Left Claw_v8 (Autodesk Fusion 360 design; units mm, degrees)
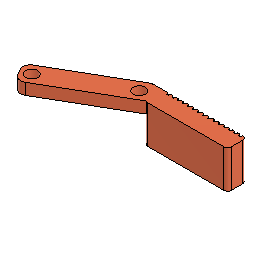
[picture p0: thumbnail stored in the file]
sketch "Sketch1" plane through (0, 0, 0) normal (0, 0, 1) x axis (1, 0, 0)
  line L1 (25, 0) -> (0, 0)
  line L2 (25, 5) -> (25, 0)
  line L3 (0, 5) -> (25, 5)
  line L4 (0, 0) -> (0, 5)
  line L5 (2.8868, 0) -> (0, 5)
  line L6 (-18.7639, -12.5) -> (2.8868, 0)
  line L7 (-21.6506, -7.5) -> (-18.7639, -12.5)
  line L8 (0, 5) -> (-21.6506, -7.5)
  line L9 (1.4434, 2.5) -> (-20.2073, -10)
  line L10 (25, 0) -> (2.8868, 0)
  line L11 (25, 5) -> (25, 0)
  line L12 (2.8868, 5) -> (25, 5)
  line L13 (2.8868, 0) -> (2.8868, 5)
  circle C1 centre (-18.0422, -8.75) radius 1.6
  circle C2 centre (0, 1.6667) radius 1.6
  point P1 (0, 0)
  point P2 (0, 0)
  point P6 (2.8868, 0)
  point P9 (-20.2073, -10)
  point P10 (1.4434, 2.5)
  point P11 (-18.0422, -8.75)
  point P12 (0, 1.6667)
  point P3 (25, 0)
  point P5 (0, 5)
  point P8 (-21.6506, -7.5)
  horizontal L1
  vertical L2
  horizontal L3
  vertical L4
  coincident P1 P2
  perpendicular L5 L6
  parallel L5 L7
  parallel L6 L8
  coincident L1 P6
  midpoint L7 P9
  midpoint L5 P10
  coincident L9 P11
  coincident L4 P12
  coincident L9 P12
  horizontal L10
  vertical L11
  horizontal L12
  vertical L13
  dimension "d1" distance P2 P3 = 25
  dimension "d2" distance P2 P5 = 5
  dimension "d3" distance P5 P8 = 25
  dimension "d4" diameter C1 = 3.2
  dimension "d5" distance L7 P11 = 2.5
  dimension "d8" angle L1 L6 = 150
  dimension "d9" diameter C2 = 3.2
extrude "Extrude1" new body sketch "Sketch1" profile of L1 L3 L4 L5 L6 L7 L8 C1 C2 L13 against normal blind 3
extrude "Extrude5" add sketch "Sketch1" profile of L1 L2 L3 L10 L11 L12 L13 against normal blind 10
sketch "Sketch2" plane through (0, 0, 0) normal (0, 0, 1) x axis (-1, 0, 0)
  line L1 (0, -5) -> (-25, -5)
  line L2 (21.6506, 7.5) -> (0, -5)
  line L3 (18.7639, 12.5) -> (21.6506, 7.5)
  line L4 (-2.8868, 0) -> (18.7639, 12.5)
  line L5 (-25, 0) -> (-2.8868, 0)
  line L6 (-25, -5) -> (-25, 0)
  line L7 (-23.4493, -4.5) -> (-23.2, -5)
  line L8 (-23.4493, -4.5) -> (-23.7507, -4.5)
  line L9 (-23.7507, -4.5) -> (-24, -5)
  line L10 (-22.3936, -4.5) -> (-22.6429, -5)
  line L11 (-22.0922, -4.5) -> (-22.3936, -4.5)
  line L12 (-22.0922, -4.5) -> (-21.8429, -5)
  line L13 (-21.0364, -4.5) -> (-21.2857, -5)
  line L14 (-20.735, -4.5) -> (-21.0364, -4.5)
  line L15 (-20.735, -4.5) -> (-20.4857, -5)
  line L16 (-19.6793, -4.5) -> (-19.9286, -5)
  line L17 (-19.3779, -4.5) -> (-19.6793, -4.5)
  line L18 (-19.3779, -4.5) -> (-19.1286, -5)
  line L19 (-18.3221, -4.5) -> (-18.5714, -5)
  line L20 (-18.0207, -4.5) -> (-18.3221, -4.5)
  line L21 (-18.0207, -4.5) -> (-17.7714, -5)
  line L22 (-16.965, -4.5) -> (-17.2143, -5)
  line L23 (-16.6636, -4.5) -> (-16.965, -4.5)
  line L24 (-16.6636, -4.5) -> (-16.4143, -5)
  line L25 (-15.6078, -4.5) -> (-15.8571, -5)
  line L26 (-15.3064, -4.5) -> (-15.6078, -4.5)
  line L27 (-15.3064, -4.5) -> (-15.0571, -5)
  line L28 (-14.2507, -4.5) -> (-14.5, -5)
  line L29 (-13.9493, -4.5) -> (-14.2507, -4.5)
  line L30 (-13.9493, -4.5) -> (-13.7, -5)
  line L31 (-12.8936, -4.5) -> (-13.1429, -5)
  line L32 (-12.5922, -4.5) -> (-12.8936, -4.5)
  line L33 (-12.5922, -4.5) -> (-12.3429, -5)
  line L34 (-11.5364, -4.5) -> (-11.7857, -5)
  line L35 (-11.235, -4.5) -> (-11.5364, -4.5)
  line L36 (-11.235, -4.5) -> (-10.9857, -5)
  line L37 (-10.1793, -4.5) -> (-10.4286, -5)
  line L38 (-9.8779, -4.5) -> (-10.1793, -4.5)
  line L39 (-9.8779, -4.5) -> (-9.6286, -5)
  line L40 (-8.8221, -4.5) -> (-9.0714, -5)
  line L41 (-8.5207, -4.5) -> (-8.8221, -4.5)
  line L42 (-8.5207, -4.5) -> (-8.2714, -5)
  line L43 (-7.465, -4.5) -> (-7.7143, -5)
  line L44 (-7.1636, -4.5) -> (-7.465, -4.5)
  line L45 (-7.1636, -4.5) -> (-6.9143, -5)
  line L46 (-6.1078, -4.5) -> (-6.3571, -5)
  line L47 (-5.8064, -4.5) -> (-6.1078, -4.5)
  line L48 (-5.8064, -4.5) -> (-5.5571, -5)
  line L49 (-4.7507, -4.5) -> (-5, -5)
  line L50 (-4.4493, -4.5) -> (-4.7507, -4.5)
  line L51 (-4.4493, -4.5) -> (-4.2, -5)
  circle C1 centre (0, -1.6667) radius 1.6
  circle C2 centre (18.0422, 8.75) radius 1.6
  horizontal L8
  dimension "d48" R-Pattern1-uDistance = 19
  dimension "d49" R-Pattern1-vDistance = 0
extrude "Extrude6" cut sketch "Sketch2" profile of L1 L7 L8 L9 L10 L11 L12 L13 L14 L15 L16 L17 L18 L19 L20 L21 L22 L23 L24 L25 L26 L27 L28 L29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 against normal blind 10
fillet "Fillet12" radius 1
fillet "Fillet13" radius 1
fillet "Fillet14" radius 2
